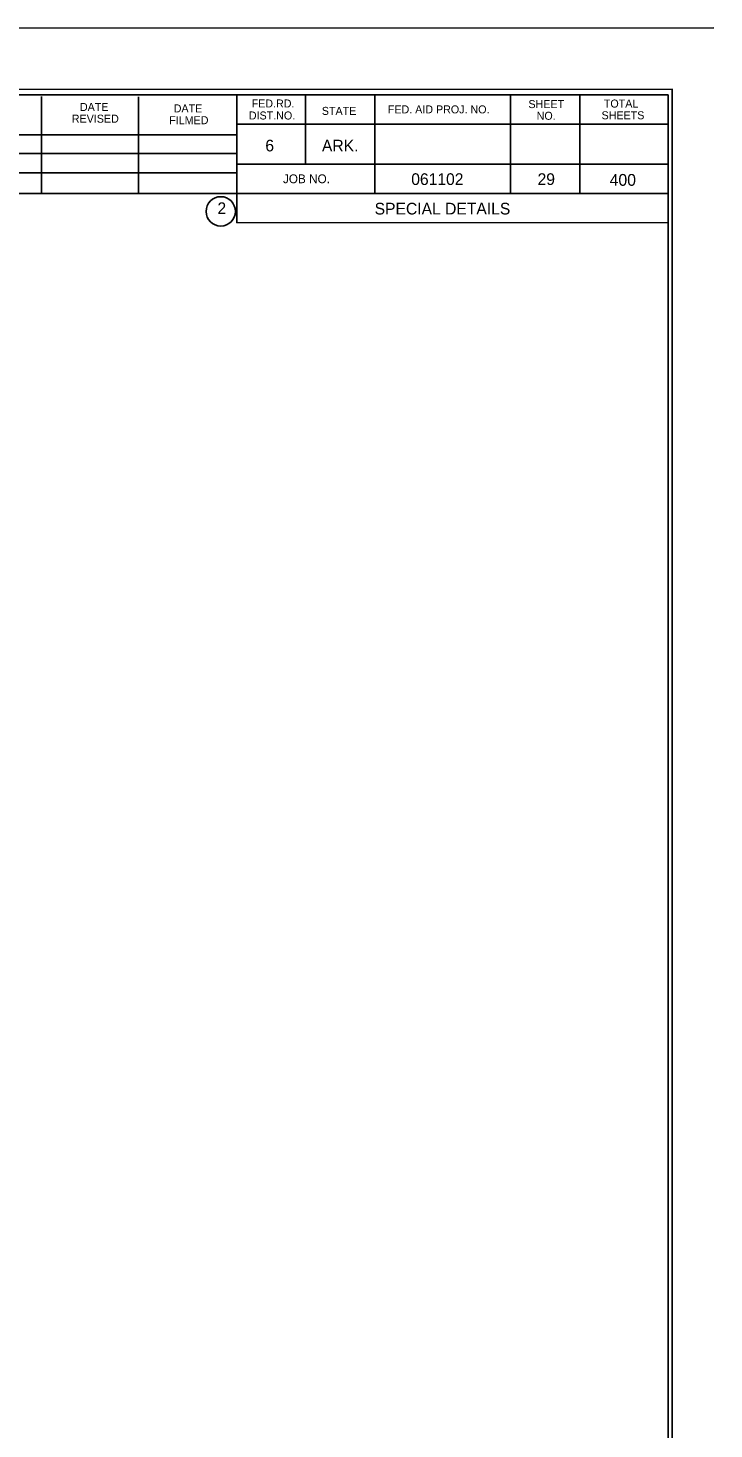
# Model space of a CAD drawing. Extents: x 714919 to 718439, y 1619644 to 1621844.
# Drawn here: x 717753 to 718439, y 1620443 to 1621844 of the extents above; entities that cross this region are included whole.
import ezdxf

# ---------------------------------------------------------------- set-up
doc = ezdxf.new("R2010")
doc.units = 0
doc.layers.add('R_Border', color=7, linetype='Continuous')
doc.layers.add('R_No Plot', color=7, linetype='Continuous')

msp = doc.modelspace()

# ---------------------------------------------------------------- linework, layer by layer
at = {"layer": 'R_Border'}
for p, q in [((718438.8, 1621843.9), (714918.8, 1621843.6)), ((715231.1, 1621777.2), (718392.9, 1621777.2)), ((717766.4, 1621678.3), (717766.4, 1621775.3)), ((717863.3, 1621678.4), (717863.3, 1621775.2)), ((717961.6, 1621777.2), (717961.8, 1621649.2)), ((718030.3, 1621777.1), (718030.2, 1621707.8)), ((718099.6, 1621777.2), (718099.6, 1621678.5)), ((718235.3, 1621777.3), (718235.3, 1621678.6)), ((718304.8, 1621777.4), (718304.8, 1621678.4)), ((718393, 1619722.6), (718392.9, 1621777.2)), ((718392.8, 1621747.6), (717961.9, 1621747.7)), ((718392.9, 1621748), (718392.9, 1621748)), ((717570.1, 1621737), (717961.7, 1621737)), ((717570.2, 1621718.4), (717961.7, 1621718.4)), ((717570.2, 1621699.1), (717961.9, 1621699.1)), ((718392.9, 1621707.8), (717961.8, 1621707.8)), ((717991.4, 1621707.8), (718392.9, 1621707.8)), ((718392.9, 1621678.4), (717570.2, 1621678.4)), ((717961.8, 1621649.2), (718392.9, 1621649.3))]:
    msp.add_line(p, q, dxfattribs=at)
msp.add_circle((717945.6, 1621660.5), 14.7, dxfattribs=at)
at = {"layer": 'R_No Plot'}
msp.add_lwpolyline([(715227, 1619717.4), (718396.9, 1619717.5), (718397, 1621782.6), (715226.9, 1621782.4)], close=True, dxfattribs=at)

# ---------------------------------------------------------------- texts
at = {"layer": 'R_Border'}
for s, height, rotation, p in [('DATE', 8, 0.0017, (717804.8, 1621760.9)), ('FED.RD.', 8, 0.0017, (717976.5, 1621764.4)), ('SHEET', 8, 0.0017, (718253.3, 1621763.8)), ('TOTAL', 8, 0.0017, (718328.7, 1621764.3)), ('REVISED', 8, 0.0017, (717796.7, 1621749.2)), ('FILMED', 8, 0.0017, (717894.1, 1621747.7)), ('DATE', 8, 0.0017, (717898.6, 1621759.5)), ('DIST.NO.', 8, 0.0017, (717973.7, 1621752.4)), ('STATE', 8, 0.0017, (718046.7, 1621757)), ('FED. AID PROJ. NO.', 8, 0.0017, (718112.7, 1621758.5)), ('NO.', 8, 0.0017, (718261.5, 1621752.1)), ('SHEETS', 8, 0.0017, (718326.4, 1621752.6)), ('6', 11.7, 0.0017, (717990.2, 1621720.5)), ('ARK.', 11.72, 0.0017, (718046.8, 1621720.4)), ('JOB NO.', 8.79, 0.0017, (718007.8, 1621688.7)), ('061102', 11.7, 0.0018, (718136.1, 1621686.9)), ('29', 11.7, 0.0018, (718262.4, 1621686.9)), ('400', 11.79, 0.0018, (718334.5, 1621686.1)), ('2', 11.7, 0.0017, (717942.3, 1621657.8)), ('SPECIAL DETAILS', 11.7, 0.0018, (718099.5, 1621657.4))]:
    msp.add_text(s, height=height, rotation=rotation, dxfattribs=at).set_placement(p)

doc.saveas('drawing.dxf')
